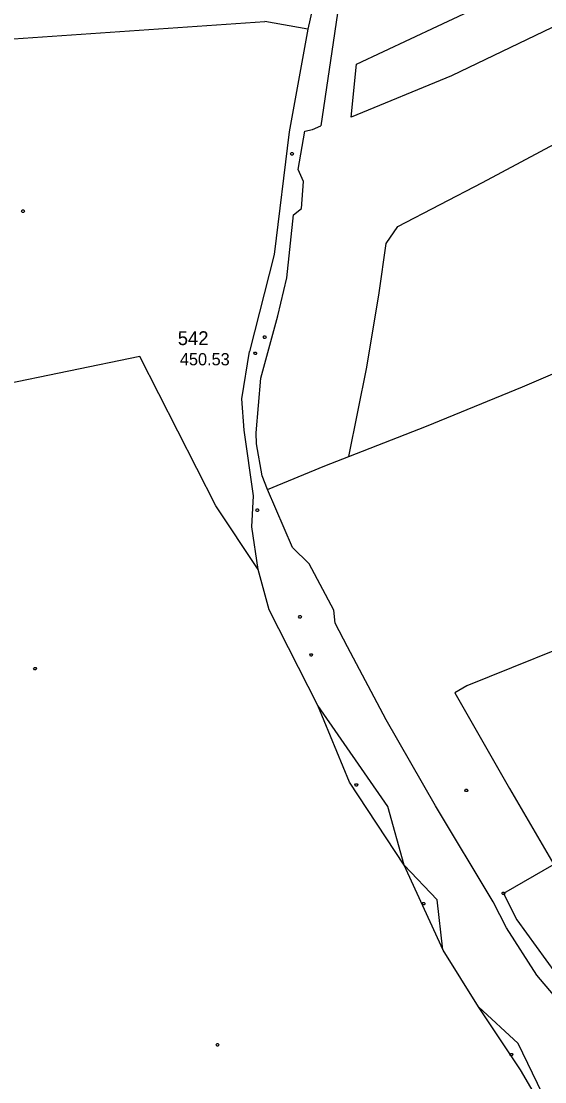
# Model space of a CAD drawing. Extents: x -664960 to -662754, y -993849 to -991145.
# Drawn here: x -663422.3 to -663293.4, y -993033.1 to -992772.1 of the extents above; entities that cross this region are included whole.
import ezdxf

# ---------------------------------------------------------------- set-up
doc = ezdxf.new("R2010")
doc.units = 0
for name, color, linetype in [('Vrstva 1', 7, 'Continuous'), ('Vrstva 12', 7, 'Continuous'), ('Vrstva 13', 7, 'Continuous'), ('Vrstva 18', 7, 'Continuous'), ('Vrstva 63', 7, 'Continuous'), ('Vrstva 8', 7, 'Continuous')]:
    doc.layers.add(name, color=color, linetype=linetype)

msp = doc.modelspace()

# ---------------------------------------------------------------- linework, layer by layer
at = {"layer": 'Vrstva 12'}
for points in [[(-663341.694, -992879.229), (-663337.234, -992857.288), (-663334.153, -992838.954), (-663332.511, -992826.79), (-663329.561, -992822.68), (-663308.772, -992811.806), (-663276.716, -992794.706), (-663246.682, -992778.908), (-663212.075, -992760.324)], [(-663361.685, -992887.35), (-663362.959, -992884.026), (-663364.403, -992876.155), (-663364.485, -992873.437), (-663363.289, -992860), (-663359.122, -992844.584), (-663356.904, -992835.271), (-663355.283, -992819.774), (-663353.274, -992818.226), (-663352.815, -992811.607), (-663354.123, -992808.583), (-663352.511, -992799.207), (-663350.574, -992798.763), (-663348.518, -992797.833)], [(-663341.694, -992879.229), (-663322.507, -992871.739), (-663298.884, -992862.11), (-663264.82, -992847.459), (-663233.108, -992834.58), (-663222.646, -992831), (-663216.562, -992854.338), (-663208.65, -992879.993), (-663205.047, -992891.622), (-663214.885, -992896.327), (-663246.058, -992908.874), (-663279.261, -992922.204), (-663312.653, -992935.665), (-663315.597, -992937.424), (-663302.153, -992960.934), (-663291.183, -992979.614), (-663303.608, -992986.729), (-663300.296, -992993.203), (-663283.685, -993016.224)], [(-663361.685, -992887.35), (-663347.562, -992881.538), (-663341.694, -992879.229)], [(-663279.937, -993029.881), (-663284.18, -993021.245), (-663286.251, -993017.598), (-663295.385, -993006.871), (-663302.847, -992995.239), (-663306.136, -992988.814), (-663320.354, -992965.17), (-663332.47, -992944.063), (-663341.969, -992926.051), (-663345.056, -992920.251), (-663345.368, -992917.078), (-663351.443, -992905.617), (-663355.536, -992901.623), (-663361.685, -992887.35)]]:
    msp.add_lwpolyline(points, dxfattribs=at)
at = {"layer": 'Vrstva 13'}
for points in [[(-663421.675, -992818.576), (-663421.495, -992818.876), (-663421.675, -992819.176), (-663422.035, -992819.176), (-663422.215, -992818.876), (-663422.035, -992818.576), (-663421.675, -992818.576)], [(-663362.162, -992849.562), (-663361.982, -992849.862), (-663362.162, -992850.162), (-663362.522, -992850.162), (-663362.702, -992849.862), (-663362.522, -992849.562), (-663362.162, -992849.562)], [(-663353.467, -992918.372), (-663353.287, -992918.672), (-663353.467, -992918.972), (-663353.827, -992918.972), (-663354.007, -992918.672), (-663353.827, -992918.372), (-663353.467, -992918.372)], [(-663350.755, -992927.751), (-663350.575, -992928.051), (-663350.755, -992928.351), (-663351.115, -992928.351), (-663351.295, -992928.051), (-663351.115, -992927.751), (-663350.755, -992927.751)], [(-663418.683, -992931.126), (-663418.503, -992931.426), (-663418.683, -992931.726), (-663419.043, -992931.726), (-663419.223, -992931.426), (-663419.043, -992931.126), (-663418.683, -992931.126)], [(-663339.629, -992959.746), (-663339.449, -992960.046), (-663339.629, -992960.346), (-663339.989, -992960.346), (-663340.169, -992960.046), (-663339.989, -992959.746), (-663339.629, -992959.746)], [(-663312.559, -992961.08), (-663312.379, -992961.38), (-663312.559, -992961.68), (-663312.919, -992961.68), (-663313.099, -992961.38), (-663312.919, -992961.08), (-663312.559, -992961.08)], [(-663323.079, -992988.936), (-663322.899, -992989.236), (-663323.079, -992989.536), (-663323.439, -992989.536), (-663323.619, -992989.236), (-663323.439, -992988.936), (-663323.079, -992988.936)], [(-663373.803, -993023.691), (-663373.623, -993023.991), (-663373.803, -993024.291), (-663374.163, -993024.291), (-663374.343, -993023.991), (-663374.163, -993023.691), (-663373.803, -993023.691)], [(-663301.481, -993026.102), (-663301.301, -993026.402), (-663301.481, -993026.702), (-663301.841, -993026.702), (-663302.021, -993026.402), (-663301.841, -993026.102), (-663301.481, -993026.102)]]:
    msp.add_lwpolyline(points, dxfattribs=at)
at = {"layer": 'Vrstva 18'}
msp.add_lwpolyline([(-663303.428, -992986.429), (-663303.248, -992986.729), (-663303.428, -992987.029), (-663303.788, -992987.029), (-663303.968, -992986.729), (-663303.788, -992986.429), (-663303.428, -992986.429)], dxfattribs=at)
at = {"layer": 'Vrstva 63'}
for points in [[(-663330.52, -992658.89), (-663331.495, -992670.602), (-663333.676, -992692.339), (-663340.522, -992724.223), (-663347.204, -992754.01), (-663351.708, -992774.127), (-663362.346, -992772.219)], [(-663323.76, -992664.43), (-663325.651, -992670.965), (-663327.75, -992690.031), (-663330.921, -992693.862), (-663336.578, -992716.329), (-663340.507, -992734.162), (-663346.25, -992764.677), (-663344.145, -992767.919), (-663348.518, -992797.833)], [(-663341.06, -992795.72), (-663339.812, -992782.68), (-663319.813, -992773.344), (-663296.571, -992762.399), (-663247.704, -992738.275), (-663192.139, -992712.934), (-663196.342, -992728.012), (-663228.245, -992742.866), (-663271.078, -992763.781), (-663316.391, -992785.583), (-663341.06, -992795.72)], [(-663480.688, -992780.627), (-663451.717, -992778.259), (-663424.184, -992776.432), (-663362.346, -992772.219)], [(-663351.708, -992774.127), (-663356.352, -992799.388), (-663360.061, -992829.507), (-663366.113, -992853.429)], [(-663355.471, -992804.459), (-663355.291, -992804.759), (-663355.471, -992805.059), (-663355.831, -992805.059), (-663356.011, -992804.759), (-663355.831, -992804.459), (-663355.471, -992804.459)], [(-663284.547, -993055.601), (-663299.44, -993030.172), (-663309.766, -993014.643), (-663318.448, -993000.715), (-663328.04, -992979.81), (-663341.459, -992959.362), (-663349.326, -992940.508), (-663361.239, -992916.927), (-663363.985, -992907.073), (-663365.563, -992896.567), (-663365.153, -992888.878), (-663367.39, -992872.717), (-663367.977, -992865.006), (-663366.113, -992853.429)], [(-663363.985, -992907.073), (-663374.41, -992891.386), (-663393.094, -992854.627), (-663428.131, -992861.855), (-663449.923, -992865.664), (-663478.672, -992868.89)], [(-663364.003, -992892.127), (-663363.823, -992892.427), (-663364.003, -992892.727), (-663364.363, -992892.727), (-663364.543, -992892.427), (-663364.363, -992892.127), (-663364.003, -992892.127)], [(-663318.507, -993000.586), (-663319.929, -992988.344), (-663328.04, -992979.81), (-663332.095, -992965.378), (-663349.326, -992940.508)], [(-663246.904, -993114.369), (-663255.353, -993101.711), (-663256.984, -993088.158), (-663273.685, -993069.79), (-663284.547, -993055.601), (-663300.016, -993023.681), (-663309.766, -993014.643)]]:
    msp.add_lwpolyline(points, dxfattribs=at)
at = {"layer": 'Vrstva 8'}
msp.add_lwpolyline([(-663364.52, -992853.54), (-663364.34, -992853.84), (-663364.52, -992854.14), (-663364.88, -992854.14), (-663365.06, -992853.84), (-663364.88, -992853.54), (-663364.52, -992853.54)], dxfattribs=at)

# ---------------------------------------------------------------- texts
at = {"layer": 'Vrstva 1'}
msp.add_text('542', height=3.4, dxfattribs=at).set_placement((-663383.768, -992851.823))
at = {"layer": 'Vrstva 63'}
msp.add_text('450.53', height=3, dxfattribs=at).set_placement((-663383.244, -992856.803))

doc.saveas('drawing.dxf')
